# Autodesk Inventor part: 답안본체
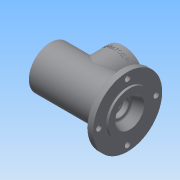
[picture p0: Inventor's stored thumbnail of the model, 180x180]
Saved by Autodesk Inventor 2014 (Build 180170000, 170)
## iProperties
Created: 2016-08
Part Number: 답안본체
Material: 일반
Document SubType Name: Modeling
Designer: net
Density: 1 g/cm^3
Appearance: 기본값
Author: net
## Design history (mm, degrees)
sketch "스케치2"
  geometry: C1 r 31 at (0, 0); 1 further point
  constraints: 1 centre point, 1 coincident
  dimensions: "d2" = 62 diameter of C1
extrude "돌출1" new body sketch "스케치2" stored distance "d3" = 115; taper "d4" = 0 deg
node "작업 평면1"
sketch "스케치3"
  geometry: C1 r 31 at (0, 0) reference; C2 r 50 at (0, 0); 1 further point
  constraints: 1 centre point, 1 coincident
  dimensions: "d6" = 100 diameter of C2
extrude "돌출2" join sketch "스케치3" distance "d7" = 10; taper "d8" = 0 deg
node "작업 평면2"
sketch "스케치4"
  geometry: L1 (57.5, -31)-(57.5, 31) reference; C1 r 30 at (1.5, 0); 1 further point
  constraints: 1 centre point
  dimensions: "d10" = 56 distance from line of L1 C1.centre; "d11" = 0 vertical distance of point (0, 0) C1.centre; "d12" = 60 diameter of C1
extrude "돌출3" join sketch "스케치4" stored distance "d13" = 10; taper "d14" = 0 deg
sketch "스케치5"
  geometry: C1 r 30 at (0, 0) reference; 1 further point
node "작업 평면3"
sketch "스케치7"
  geometry: C1 r 26 at (0, 0); 1 further point
  constraints: 1 centre point, 1 coincident
  dimensions: "d52" = 52 diameter of C1
extrude "돌출4" cut sketch "스케치7" stored distance "d53" = 38; taper "d54" = 0 deg
sketch "스케치8"
  geometry: 1 further point
sketch "스케치9"
  geometry: L1 (57.5, -31)-(57.5, 31) reference; L2 (-57.5, 31)-(-57.5, -31) reference; L3 (57.5, 0)-(20.969, 0); L4 (57.5, 21)-(43.5, 16); L5 (17.5, -26)-(17.5, 26) reference; L6 (28.5, 16.5)-(28.5, 17.5); L7 (33.5, 16.5)-(28.5, 16.5); L8 (28.5, 17.5)-(17.5, 17.5); L9 (33.5, 10)-(33.5, 16.5); L10 (42.8, 12.5)-(36.2, 12.5); L11 (43.5, 16)-(43.5, 12.904); L12 (-57.5, 31)-(44.5, 31) reference; L13 (36.2, 10)-(33.5, 10); L14 (36.2, 12.5)-(36.2, 10); L15 (57.5, 21)-(57.5, 0); L16 (57.5, 0)-(17.5, 0); L17 (42.8, 12.5)-(43.5, 12.904); 1 further point
  constraints: 26 end point, 5 parallel, 2 midpoint, 2 perpendicular, 2 point on line, 1 collinear
  dimensions: "d58" = 21 distance of L3.start L4.start; "d61" = 11 distance between parallel lines of L6 L5; "d65" = 16 distance from line of L3 L4.end; "d67" = 12.5 distance between parallel lines of L3 L10; "d68" = 10 distance between parallel lines of L3 L13; "d71" = 6.5 distance of L9.start L7.start; "d73" = 17.5 distance between parallel lines of L3 L8; "d150" = 24 distance from line of L9 L4.start; "d151" = 2.7 distance between parallel lines of L9 L14; "d152" = 5 distance of L7.start L6.start; "d153" = 14 horizontal distance of L4.start L4.end; "d155" = 30 deg angle of L10 L17; "d156" = 0.7 horizontal distance of L10.start L11.end
revolve "회전1" sketch "스케치9" stored, may be unused: angle "d74" = 90 deg
sketch "스케치10"
  geometry: 1 further point
hole "구멍1" diameter "d77" = 40.376; stored, may be unused: countersink angle "d81" = 90 deg, drill point angle "d83" = 0 deg; dims "d78" = 9, "d79" = 4, "d80" = 2, "d82" = 9, "d132" = 10, "d133" = 10
sketch "스케치11"
  geometry: C1 r 20.188 at (0, 0) reference; C2 r 24 at (0, 0)
  constraints: 1 centre point, 1 coincident
  dimensions: "d84" = 48 diameter of C2
extrude "돌출5" cut sketch "스케치11" distance "d85" = 3; taper "d86" = 0 deg
sketch "스케치12"
  geometry: C1 r 24 at (0, 0) reference; C2 r 20 at (0, 0)
  constraints: 1 centre point, 1 coincident
  dimensions: "d87" = 40 diameter of C2
extrude "돌출6" cut sketch "스케치12" distance "d88" = 9; taper "d89" = 0 deg
sketch "스케치13"
  geometry: C1 r 20 at (0, 0) reference; C2 r 17.5 at (0, 0)
  constraints: 1 centre point, 1 coincident
  dimensions: "d90" = 35 diameter of C2
sketch "스케치15"
  geometry: C1 r 30 at (0, 0) reference; C2 r 19 at (0, 0); 1 further point
  constraints: 1 centre point, 1 coincident
  dimensions: "d96" = 38 diameter of C2
extrude "돌출9" cut sketch "스케치15" stored distance "d97" = 1.75; taper "d98" = 0 deg
sketch "스케치16" dims "d99" = 48
  geometry: L1 (0, 24)-(0, 0); C1 r 30 at (0, 0) reference; 2 further points
  constraints: 2 coincident, 2 end point, 1 vertical, 1 vertical alignment, 2 other
hole "구멍2" sketch "스케치16" at (0, 24) diameter "d100" = 4; stored, may be unused: countersink angle "d104" = 90 deg, drill point angle "d106" = 118 deg; dims "d101" = 9, "d102" = 4, "d103" = 2, "d105" = 10
feature "스레드1" dims "d107" = 8, "d108" = 0
sketch "스케치17" dims "d112" = 83
  geometry: L1 (0, 0)-(0, 41.5); C1 r 50 at (0, 0) reference; 1 further point
  constraints: 2 coincident, 2 end point, 1 vertical, 1 vertical alignment, 2 other
hole "구멍3" sketch "스케치17" at (0, 41.5) diameter "d113" = 8; stored, may be unused: countersink angle "d117" = 90 deg, drill point angle "d119" = 118 deg; dims "d114" = 9, "d115" = 4, "d116" = 2, "d118" = 10
fillet "모깎기1" dims "d123" = 3
node "작업 평면4"
sketch "스케치18"
  geometry: L1 (-31.5, 50)-(-31.5, 31) reference; L2 (-57.5, 31)-(-57.5, -31) reference; L3 (-31.5, 50)-(28.5, 50) reference; 2 further points
  constraints: 1 other
  dimensions: "d126" = 56 distance from line of point (-1.5, 40) L2; "d127" = 10 distance from line of point (-1.5, 40) L3
feature "엠보싱1" sketch "스케치18" dims "d2" = 62, "d128" = 0.5, "d129" = 0
fillet "모깎기2" dims "d130" = 3
fillet "모깎기3" dims "d131" = 3
extrude "돌출10" cut sketch "스케치13" distance "d134" = 3.25; taper "d135" = 0 deg
sketch "스케치19"
  geometry: C1 r 17.5 at (0, 0) reference; C2 r 18.5 at (0, 0)
  constraints: 1 centre point, 1 coincident
  dimensions: "d136" = 37 diameter of C2
extrude "돌출11" cut sketch "스케치19" distance "d137" = 1.75; taper "d138" = 0 deg
sketch "스케치20"
  geometry: C1 r 18.5 at (0, 0) reference; C2 r 17.5 at (0, 0)
  constraints: 1 centre point, 1 coincident
  dimensions: "d139" = 35 diameter of C2
extrude "돌출12" cut sketch "스케치20" distance "d140" = 15; taper "d141" = 0 deg
fillet "모깎기4" dims "d142" = 3
fillet "모깎기5" dims "d146" = 0.3
fillet "모깎기6" dims "d147" = 0.3
fillet "모깎기7" dims "d148" = 3
fillet "모깎기8" dims "d149" = 3
node "솔리드1"
pattern_circular "원형 패턴1" dims angle "d110" = 360 deg
pattern_circular "원형 패턴2" dims angle "d121" = 360 deg
other parameters: "d5" = -3, "d51" = -56, "d55" = 21, "d57" = 16, "d62" = 16.5, "d63" = 16.5, "d64" = 17.5
